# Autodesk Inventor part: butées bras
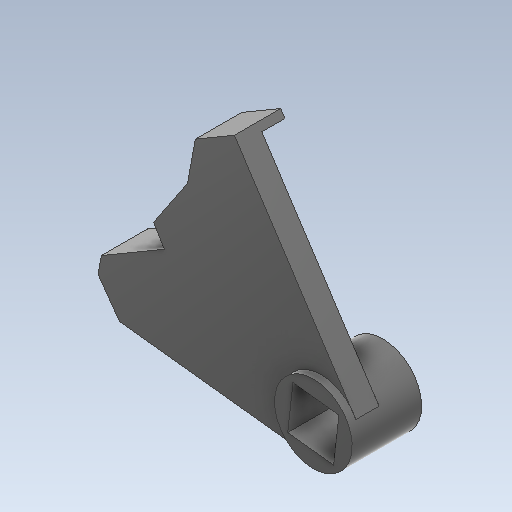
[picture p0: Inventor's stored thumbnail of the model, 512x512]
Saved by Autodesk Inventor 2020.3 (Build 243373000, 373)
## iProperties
Created: 2020-09
Part Number: butées bras
Material: Plastique ABS
Document SubType Name: Modeling
Designer: ficho
Density: 1.06 g/cm^3
Appearance: Lisse - Noir
Mass: 2.15613 g
Surface Area: 20.0678 cm^2
Volume: 2.03408 cm^3
Author: ficho
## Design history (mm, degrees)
sketch "Esquisse1"
  geometry: L1 (0, 0)-(102.973, 0); L2 (102.973, 0)-(102.973, -47.196); L3 (102.973, -47.196)-(0, -47.196); L4 (0, -47.196)-(0, 0); L5 (52.479, -7.625)-(47.422, -10.592); L6 (47.422, -10.592)-(46.411, -16.054); L7 (46.411, -16.054)-(42.028, -22.594); L8 (42.028, -22.594)-(43.405, -24.942); L9 (43.405, -24.942)-(35.257, -29.722); L10 (35.257, -29.722)-(34.826, -32.049); L11 (34.826, -32.049)-(37.605, -35.942); L12 (37.605, -35.942)-(63.134, -38.868); L13 (68.213, -31.643)-(52.479, -7.625); A1 r 5.028 centre (63.706, -33.873) between (63.134, -38.868) and (68.213, -31.643); 2 further points; 1 other entity
  constraints: 18 end point, 2 perpendicular, 2 point on circle, 1 centre point, 1 parallel, 1 tangent, 2 other
  dimensions: "d1" = 528.8537 distance of point (1033.329, -611.314) point (829.373, -123.37); "d2" = 102.97341 distance between parallel lines of L2 L4
extrude "Extrusion1" new body sketch "Esquisse1" distance "d3" = 3; taper "d4" = 0 deg
sketch "Esquisse2"
  geometry: C1 r 5.028 at (63.706, -33.873); A1 r 5.028 centre (63.706, -33.873) between (63.134, -38.868) and (68.213, -31.643) reference; 3 further points
  constraints: 1 centre point, 1 coincident, 1 concentric
extrude "Extrusion2" join sketch "Esquisse2" distance "d5" = 1; taper "d6" = 0 deg
sketch "Esquisse3"
  geometry: A1 r 5.028 centre (-63.706, -33.873) between (-68.213, -31.643) and (-63.134, -38.868) reference; 3 further points
  constraints: 1 coincident, 3 other
extrude "Extrusion3" join sketch "Esquisse3" distance "d7" = 5; taper "d8" = 0 deg
sketch "Esquisse4"
  geometry: L1 (-52.479, -7.625)-(-47.422, -10.592) reference; L2 (-47.422, -10.592)-(-46.411, -16.054) reference; L3 (-43.405, -24.942)-(-35.257, -29.722) reference; L4 (-35.257, -29.722)-(-34.826, -32.049) reference; L5 (-43.911, -25.804)-(-36.157, -30.353); L6 (-36.157, -30.353)-(-35.81, -32.231); L7 (-53.028, -8.462)-(-48.322, -11.223); L8 (-48.322, -11.223)-(-47.428, -16.054); L9 (-46.411, -16.054)-(-47.428, -16.054); L10 (-67.551, -30.632)-(-52.479, -7.625) reference; L11 (-53.028, -8.462)-(-52.479, -7.625); L12 (-52.479, -7.625)-(-47.422, -10.592); L13 (-47.422, -10.592)-(-46.411, -16.054); L14 (-35.81, -32.231)-(-34.826, -32.049); L15 (-34.826, -32.049)-(-35.257, -29.722); L16 (-35.257, -29.722)-(-43.405, -24.942); L17 (-43.405, -24.942)-(-43.911, -25.804); 2 further points
  constraints: 24 end point, 3 perpendicular, 2 collinear, 1 horizontal, 1 parallel, 1 point on line, 2 other
  dimensions: "d9" = 1 distance between parallel lines of L3 L5; "d10" = 1 distance between parallel lines of L1 L7
extrude "Extrusion4" join sketch "Esquisse4" distance "d11" = 3; taper "d12" = 0 deg
sketch "Esquisse5"
  geometry: L1 (2.639, -3.322)-(-3.322, -2.639); L2 (-3.322, -2.639)-(-2.639, 3.322); L3 (-2.639, 3.322)-(3.322, 2.639); L4 (3.322, 2.639)-(2.639, -3.322); L5 (-26.101, -2.07)-(-0.573, -4.995) reference; C1 r 5.028 at (0, 0) reference; 1 further point
  constraints: 8 end point, 2 parallel, 2 perpendicular
  dimensions: "d13" = 6 distance between parallel lines of L2 L4; "d14" = 6 distance between parallel lines of L3 L1; "d15" = 3 distance from line of C1.centre L1; "d16" = 3 distance from line of C1.centre L4
extrude "Extrusion5" cut sketch "Esquisse5" distance "d17" = 7.5; taper "d18" = 0 deg
sketch "Esquisse6"
  geometry: C1 r 5.028 at (0, 0) reference; 1 further point
hole "Perçage1" sketch "Esquisse6" at (0, 0) diameter "d19" = 2.013; stored, may be unused: countersink angle "d23" = 90 deg, drill point angle "d25" = 118 deg; dims "d20" = 5, "d21" = 4, "d22" = 2, "d24" = 6
node "Solide1"
node "Image1"
node "Boucle projetée1"
